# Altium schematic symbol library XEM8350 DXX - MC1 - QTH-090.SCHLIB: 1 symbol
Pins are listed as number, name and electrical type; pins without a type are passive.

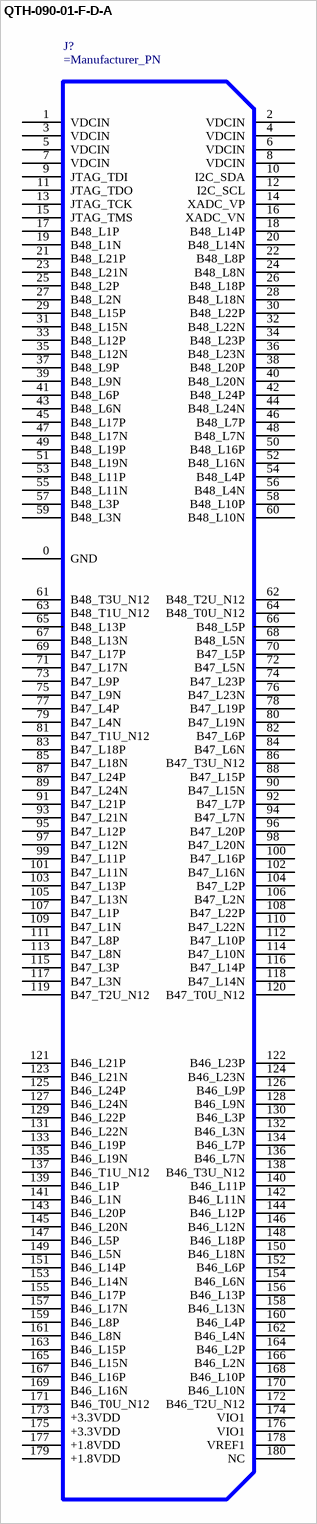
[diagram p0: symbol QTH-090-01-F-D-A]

## QTH-090-01-F-D-A
designator J?
0.5mm Double Row High Speed Socket Assembly
pins: 0 GND (power), 1 VDCIN, 2 VDCIN, 3 VDCIN, 4 VDCIN, 5 VDCIN, 6 VDCIN, 7 VDCIN, 8 VDCIN, 9 JTAG_TDI, 10 I2C_SDA, 11 JTAG_TDO, 12 I2C_SCL, 13 JTAG_TCK, 14 XADC_VP, 15 JTAG_TMS, 16 XADC_VN, 17 B48_L1P, 18 B48_L14P, 19 B48_L1N, 20 B48_L14N, 21 B48_L21P, 22 B48_L8P, 23 B48_L21N, 24 B48_L8N, 25 B48_L2P, 26 B48_L18P, 27 B48_L2N, 28 B48_L18N, 29 B48_L15P, 30 B48_L22P, 31 B48_L15N, 32 B48_L22N, 33 B48_L12P, 34 B48_L23P, 35 B48_L12N, 36 B48_L23N, 37 B48_L9P, 38 B48_L20P, 39 B48_L9N, 40 B48_L20N, 41 B48_L6P, 42 B48_L24P, 43 B48_L6N, 44 B48_L24N, 45 B48_L17P, 46 B48_L7P, 47 B48_L17N, 48 B48_L7N, 49 B48_L19P, 50 B48_L16P, 51 B48_L19N, 52 B48_L16N, 53 B48_L11P, 54 B48_L4P, 55 B48_L11N, 56 B48_L4N, 57 B48_L3P, 58 B48_L10P, 59 B48_L3N, 60 B48_L10N, 61 B48_T3U_N12, 62 B48_T2U_N12, 63 B48_T1U_N12, 64 B48_T0U_N12, 65 B48_L13P, 66 B48_L5P, 67 B48_L13N, 68 B48_L5N, 69 B47_L17P, 70 B47_L5P, 71 B47_L17N, 72 B47_L5N, 73 B47_L9P, 74 B47_L23P, 75 B47_L9N, 76 B47_L23N, 77 B47_L4P, 78 B47_L19P, 79 B47_L4N, 80 B47_L19N, 81 B47_T1U_N12, 82 B47_L6P, 83 B47_L18P, 84 B47_L6N, 85 B47_L18N, 86 B47_T3U_N12, 87 B47_L24P, 88 B47_L15P, 89 B47_L24N, 90 B47_L15N, 91 B47_L21P, 92 B47_L7P, 93 B47_L21N, 94 B47_L7N, 95 B47_L12P, 96 B47_L20P, 97 B47_L12N, 98 B47_L20N, 99 B47_L11P, 100 B47_L16P, 101 B47_L11N, 102 B47_L16N, 103 B47_L13P, 104 B47_L2P, 105 B47_L13N, 106 B47_L2N, 107 B47_L1P, 108 B47_L22P, 109 B47_L1N, 110 B47_L22N, 111 B47_L8P, 112 B47_L10P, 113 B47_L8N, 114 B47_L10N, 115 B47_L3P, 116 B47_L14P, 117 B47_L3N, 118 B47_L14N, 119 B47_T2U_N12, 120 B47_T0U_N12, 121 B46_L21P, 122 B46_L23P, 123 B46_L21N, 124 B46_L23N, 125 B46_L24P, 126 B46_L9P, 127 B46_L24N, 128 B46_L9N, 129 B46_L22P, 130 B46_L3P, 131 B46_L22N, 132 B46_L3N, 133 B46_L19P, 134 B46_L7P, 135 B46_L19N, 136 B46_L7N, 137 B46_T1U_N12, 138 B46_T3U_N12, 139 B46_L1P, 140 B46_L11P, 141 B46_L1N, 142 B46_L11N, 143 B46_L20P, 144 B46_L12P, 145 B46_L20N, 146 B46_L12N, 147 B46_L5P, 148 B46_L18P, 149 B46_L5N, 150 B46_L18N, 151 B46_L14P, 152 B46_L6P, 153 B46_L14N, 154 B46_L6N, 155 B46_L17P, 156 B46_L13P, 157 B46_L17N, 158 B46_L13N, 159 B46_L8P, 160 B46_L4P, 161 B46_L8N, 162 B46_L4N, 163 B46_L15P, 164 B46_L2P, 165 B46_L15N, 166 B46_L2N, 167 B46_L16P, 168 B46_L10P, 169 B46_L16N, 170 B46_L10N, 171 B46_T0U_N12, 172 B46_T2U_N12, 173 +3.3VDD, 174 VIO1, 175 +3.3VDD, 176 VIO1, 177 +1.8VDD, 178 VREF1, 179 +1.8VDD, 180 NC
1 alternate drawing of the same symbol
